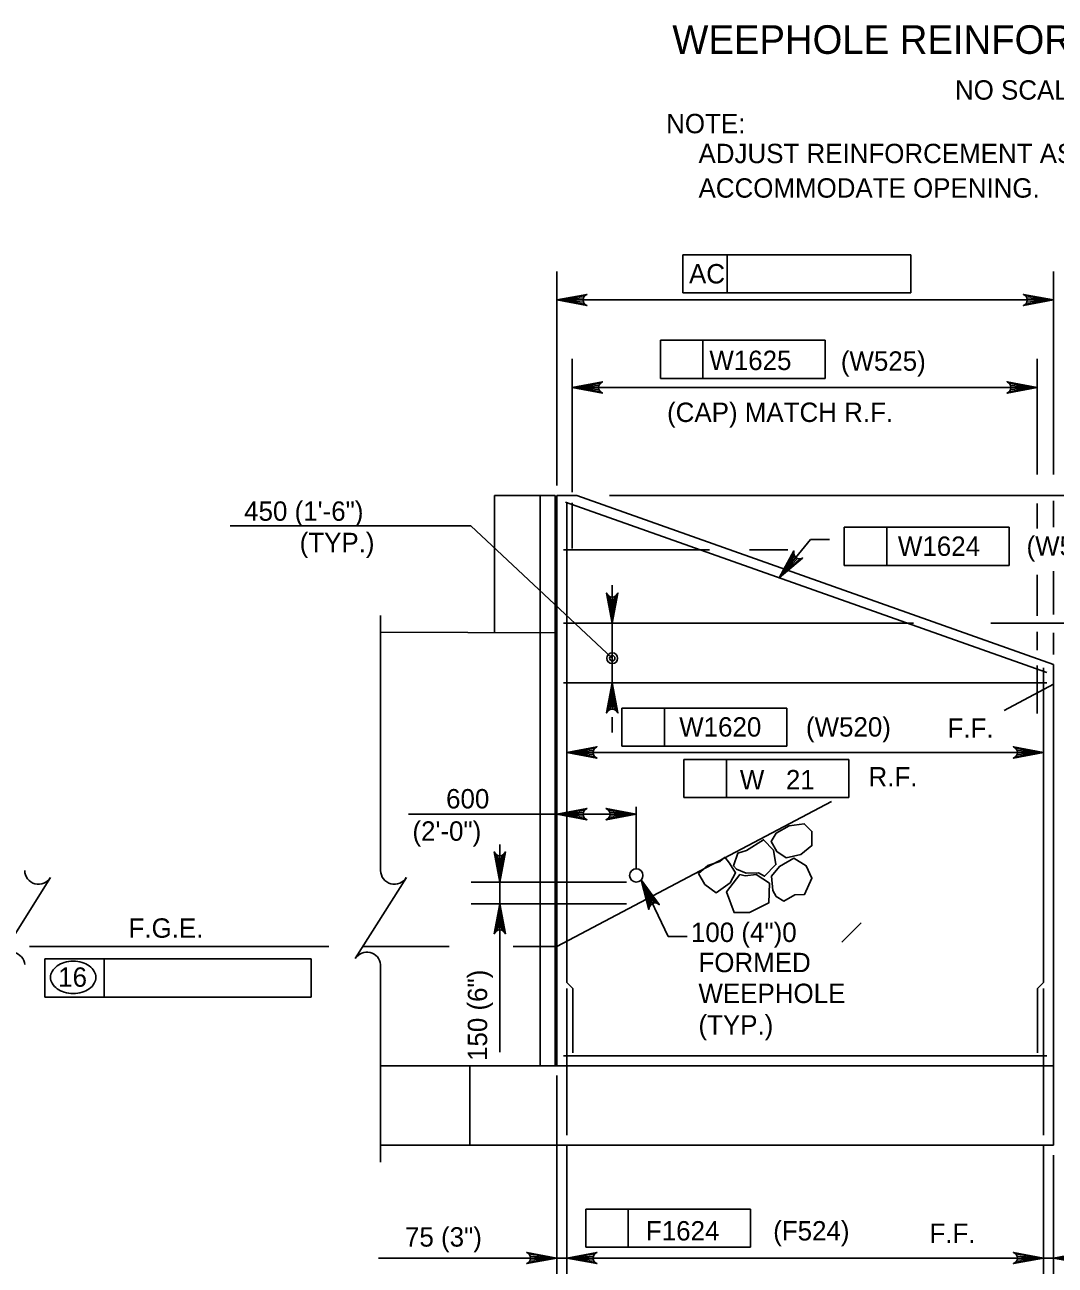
# Model space of a CAD drawing. Extents: x 638340 to 640241, y 295465 to 298435.
# Drawn here: x 639576.7 to 639736.2, y 297942.1 to 298134.1 of the extents above; entities that cross this region are included whole.
import ezdxf

# ---------------------------------------------------------------- set-up
doc = ezdxf.new("R2010")
doc.units = 0
for name, color, linetype in [('10', 7, 'Continuous'), ('3', 7, 'Continuous'), ('4', 7, 'Continuous'), ('5', 7, 'Continuous'), ('6', 7, 'Continuous')]:
    doc.layers.add(name, color=color, linetype=linetype)

# ---------------------------------------------------------------- blocks, each defined once
blk = doc.blocks.new('ROCK')
at = {"layer": '4'}
for points in [[(2.36725, 1.088), (2.2065, 0.82625), (2.378625, 0.506625), (2.66975, 0.3095), (3.128875, 0.403375), (3.48475, 0.6775), (3.4915, 1.123375), (3.25625, 1.36725), (2.783625, 1.308375)], [(1.10175, -0.02725), (1.4015, -0.159125), (1.78825, -0.148875), (1.980875, -0.266), (2.343375, 0.09475), (2.27875, 0.5505), (1.969375, 0.883), (1.4225, 0.553625), (1.152875, 0.479), (1.0105, 0.082)], [(0.74675, 0.359875), (0.882, 0.16), (1.072875, -0.144), (0.892, -0.457375), (0.448125, -0.758625), (0.1, -0.49325), (-0.095, -0.146375), (0.202875, 0.1025), (0.579125, 0.219875)], [(2.231375, -0.71725), (2.2025, -0.266375), (2.45475, 0.037125), (2.9085, 0.28875), (3.2995, 0.047625), (3.46875, -0.344), (3.231625, -0.855), (2.92, -0.860375), (2.5765, -1.054625), (2.340375, -0.904375)], [(1.2085, -0.192875), (0.778375, -0.737625), (1.008375, -1.391375), (1.48725, -1.396875), (2.09825, -1.106625), (2.133375, -0.486375), (1.723125, -0.203375), (1.37425, -0.239875)]]:
    blk.add_lwpolyline(points, close=True, dxfattribs=at)

msp = doc.modelspace()

# ---------------------------------------------------------------- linework, layer by layer
at = {"layer": '10'}
for p, q in [((639658.78, 298061.25), (639649.36, 298061.25)), ((639649.36, 298061.25), (639649.36, 298039.98)), ((639656.44, 298061.25), (639656.44, 297972.97)), ((639658.78, 298061.25), (639658.78, 297972.97)), ((639659.03, 298061.25), (639659.03, 297972.97)), ((639662.11, 298061.25), (639659.03, 298061.25)), ((639735.93, 298035.1), (639662.11, 298061.25)), ((639631.76, 298040.08), (639658.78, 298039.96)), ((639735.93, 298035.1), (639735.93, 297960.67)), ((639728.27, 298027.98), (639735.93, 298032.03)), ((639659.03, 297991.43), (639701.57, 298013.89)), ((639629.01, 297991.43), (639642.39, 297991.43)), ((639652.28, 297991.43), (639659.03, 297991.43)), ((639631.76, 297972.97), (639735.93, 297972.97)), ((639645.56, 297972.97), (639645.56, 297960.67)), ((639631.76, 297960.67), (639735.93, 297960.67))]:
    msp.add_line(p, q, dxfattribs=at)
at = {"layer": '3'}
for p, q in [((639645.74, 298056.56), (639608.46, 298056.56)), ((639631.76, 298042.66), (639631.76, 298003.19)), ((639580.65, 298002.12), (639572.75, 297989.56)), ((639635.74, 298002.12), (639627.83, 297989.56)), ((639631.76, 297988.62), (639631.76, 297958.04))]:
    msp.add_line(p, q, dxfattribs=at)
for radius in [0.833, 0.417]:
    msp.add_circle((639667.62, 298036.05), radius, dxfattribs=at)
for centre, start, end in [((639578.8, 298003.19), 180, 330), ((639633.89, 298003.19), 180, 330), ((639574.55, 297988.42), 5.3286, 147.8672), ((639629.64, 297988.42), 5.3286, 147.8672)]:
    msp.add_arc(centre, 2.13, start, end, dxfattribs=at)
at = {"layer": '4'}
for p, q in [((639678.55, 298098.51), (639713.86, 298098.51)), ((639678.55, 298092.6), (639678.55, 298098.51)), ((639685.4, 298092.6), (639685.4, 298098.51)), ((639713.86, 298098.51), (639713.86, 298092.6)), ((639659.03, 298062.79), (639659.03, 298095.94)), ((639735.93, 298064.49), (639735.93, 298095.94)), ((639713.86, 298092.6), (639678.55, 298092.6)), ((639661.98, 298091.52), (639732.98, 298091.52)), ((639675.06, 298085.27), (639700.6, 298085.27)), ((639675.06, 298079.36), (639675.06, 298085.27)), ((639681.66, 298079.36), (639681.66, 298085.27)), ((639700.6, 298085.27), (639700.6, 298079.36)), ((639661.43, 298061.76), (639661.43, 298082.41)), ((639733.4, 298064.49), (639733.4, 298082.41)), ((639700.6, 298079.36), (639675.06, 298079.36)), ((639661.43, 298077.98), (639733.4, 298077.98)), ((639667.17, 298061.25), (639852.81, 298061.25)), ((639733.4, 298056.16), (639733.4, 298060.02)), ((639735.93, 298056.36), (639735.93, 298060.42)), ((639645.74, 298056.56), (639667.62, 298036.05)), ((639703.53, 298056.32), (639729.07, 298056.32)), ((639703.53, 298050.41), (639703.53, 298056.32)), ((639710.13, 298050.41), (639710.13, 298056.32)), ((639729.07, 298056.32), (639729.07, 298050.41)), ((639693.44, 298048.52), (639698.32, 298054.42)), ((639698.32, 298054.42), (639701.27, 298054.42)), ((639688.88, 298052.84), (639694.81, 298052.84)), ((639729.07, 298050.41), (639703.53, 298050.41)), ((639733.4, 298042.61), (639733.4, 298048.98)), ((639735.93, 298042.81), (639735.93, 298049.55)), ((639667.62, 298044.42), (639667.62, 298047.37)), ((639667.62, 298041.47), (639667.62, 298032.24)), ((639726.21, 298041.47), (639740.19, 298041.47)), ((639733.4, 298037.32), (639733.4, 298040.13)), ((639735.93, 298036.64), (639735.93, 298039.99)), ((639669.1, 298028.34), (639694.64, 298028.34)), ((639669.1, 298022.43), (639669.1, 298028.34)), ((639675.69, 298022.43), (639675.69, 298028.34)), ((639694.64, 298028.34), (639694.64, 298022.43)), ((639667.62, 298026.92), (639667.62, 298024.53)), ((639660.57, 298021.47), (639734.39, 298021.47)), ((639694.64, 298022.43), (639669.1, 298022.43)), ((639678.72, 298020.4), (639704.26, 298020.4)), ((639678.72, 298014.49), (639678.72, 298020.4)), ((639685.31, 298014.49), (639685.31, 298020.4)), ((639704.26, 298020.4), (639704.26, 298014.49)), ((639704.26, 298014.49), (639678.72, 298014.49)), ((639636.07, 298011.92), (639671.34, 298011.92)), ((639671.34, 298003.45), (639671.34, 298013.06)), ((639650.21, 297975.06), (639650.21, 298007.2)), ((639669.8, 298001.4), (639645.78, 298001.4)), ((639672.11, 298001.75), (639676.25, 297992.96)), ((639669.8, 297998.05), (639645.78, 297998.05)), ((639703.14, 297992.09), (639706.13, 297995.08)), ((639676.25, 297992.96), (639679.2, 297992.96)), ((639623.75, 297991.43), (639577.42, 297991.43)), ((639579.79, 297989.49), (639621, 297989.49)), ((639579.79, 297983.59), (639579.79, 297989.49)), ((639588.96, 297983.59), (639588.96, 297989.49)), ((639621, 297989.49), (639621, 297983.59)), ((639621, 297983.59), (639579.79, 297983.59)), ((639659.03, 297971.43), (639659.03, 297938.76)), ((639660.57, 297960.67), (639660.57, 297938.76)), ((639734.39, 297960.67), (639734.39, 297938.76)), ((639735.93, 297959.13), (639735.93, 297938.76)), ((639663.5, 297950.78), (639689.04, 297950.78)), ((639663.5, 297944.88), (639663.5, 297950.78)), ((639670.09, 297944.88), (639670.09, 297950.78)), ((639689.04, 297950.78), (639689.04, 297944.88)), ((639689.04, 297944.88), (639663.5, 297944.88)), ((639653.13, 297943.19), (639631.42, 297943.19)), ((639656.08, 297943.19), (639653.13, 297943.19)), ((639660.57, 297943.19), (639659.03, 297943.19)), ((639659.91, 297943.19), (639662.87, 297943.19)), ((639663.52, 297943.19), (639731.44, 297943.19)), ((639663.52, 297943.19), (639666.48, 297943.19)), ((639731.44, 297943.19), (639728.49, 297943.19)), ((639734.39, 297943.19), (639735.93, 297943.19))]:
    msp.add_line(p, q, dxfattribs=at)
for points in [[(639659.03, 298091.52), (639663.69, 298092.39), (639663.33, 298092.14), (639663.15, 298091.83), (639663.1, 298091.52), (639663.15, 298091.2), (639663.33, 298090.89), (639663.69, 298090.64), (639659.03, 298091.52), (639663.33, 298090.89), (639663.15, 298091.2), (639659.03, 298091.52), (639663.1, 298091.52), (639663.15, 298091.83), (639659.03, 298091.52), (639663.33, 298092.14)], [(639735.93, 298091.52), (639731.27, 298090.64), (639731.63, 298090.89), (639731.81, 298091.2), (639731.87, 298091.52), (639731.81, 298091.83), (639731.63, 298092.14), (639731.27, 298092.39), (639735.93, 298091.52), (639731.63, 298092.14), (639731.81, 298091.83), (639735.93, 298091.52), (639731.87, 298091.52), (639731.81, 298091.2), (639735.93, 298091.52), (639731.63, 298090.89)], [(639661.43, 298077.98), (639666.09, 298078.86), (639665.73, 298078.61), (639665.55, 298078.3), (639665.49, 298077.98), (639665.55, 298077.67), (639665.73, 298077.36), (639666.09, 298077.11), (639661.43, 298077.98), (639665.73, 298077.36), (639665.55, 298077.67), (639661.43, 298077.98), (639665.49, 298077.98), (639665.55, 298078.3), (639661.43, 298077.98), (639665.73, 298078.61)], [(639733.4, 298077.98), (639728.74, 298077.11), (639729.1, 298077.36), (639729.28, 298077.67), (639729.34, 298077.98), (639729.28, 298078.3), (639729.1, 298078.61), (639728.74, 298078.86), (639733.4, 298077.98), (639729.1, 298078.61), (639729.28, 298078.3), (639733.4, 298077.98), (639729.34, 298077.98), (639729.28, 298077.67), (639733.4, 298077.98), (639729.1, 298077.36)], [(639693.44, 298048.52), (639695.73, 298052.67), (639695.7, 298052.24), (639695.82, 298051.89), (639696.03, 298051.65), (639696.3, 298051.49), (639696.66, 298051.44), (639697.08, 298051.56), (639693.44, 298048.52), (639696.66, 298051.44), (639696.3, 298051.49), (639693.44, 298048.52), (639696.03, 298051.65), (639695.82, 298051.89), (639693.44, 298048.52), (639695.7, 298052.24)], [(639667.62, 298041.47), (639666.75, 298046.13), (639666.99, 298045.77), (639667.31, 298045.58), (639667.62, 298045.53), (639667.93, 298045.58), (639668.24, 298045.77), (639668.49, 298046.13), (639667.62, 298041.47), (639668.24, 298045.77), (639667.93, 298045.58), (639667.62, 298041.47), (639667.62, 298045.53), (639667.31, 298045.58), (639667.62, 298041.47), (639666.99, 298045.77)], [(639667.62, 298032.24), (639668.49, 298027.58), (639668.24, 298027.94), (639667.93, 298028.12), (639667.62, 298028.18), (639667.31, 298028.12), (639666.99, 298027.94), (639666.75, 298027.58), (639667.62, 298032.24), (639666.99, 298027.94), (639667.31, 298028.12), (639667.62, 298032.24), (639667.62, 298028.18), (639667.93, 298028.12), (639667.62, 298032.24), (639668.24, 298027.94)], [(639660.57, 298021.47), (639665.23, 298022.34), (639664.87, 298022.09), (639664.69, 298021.78), (639664.63, 298021.47), (639664.69, 298021.16), (639664.87, 298020.84), (639665.23, 298020.6), (639660.57, 298021.47), (639664.87, 298020.84), (639664.69, 298021.16), (639660.57, 298021.47), (639664.63, 298021.47), (639664.69, 298021.78), (639660.57, 298021.47), (639664.87, 298022.09)], [(639734.39, 298021.47), (639729.73, 298020.6), (639730.09, 298020.84), (639730.28, 298021.16), (639730.33, 298021.47), (639730.28, 298021.78), (639730.09, 298022.09), (639729.73, 298022.34), (639734.39, 298021.47), (639730.09, 298022.09), (639730.28, 298021.78), (639734.39, 298021.47), (639730.33, 298021.47), (639730.28, 298021.16), (639734.39, 298021.47), (639730.09, 298020.84)], [(639659.03, 298011.92), (639663.69, 298012.79), (639663.33, 298012.54), (639663.15, 298012.23), (639663.1, 298011.92), (639663.15, 298011.6), (639663.33, 298011.29), (639663.69, 298011.04), (639659.03, 298011.92), (639663.33, 298011.29), (639663.15, 298011.6), (639659.03, 298011.92), (639663.1, 298011.92), (639663.15, 298012.23), (639659.03, 298011.92), (639663.33, 298012.54)], [(639671.34, 298011.92), (639666.67, 298011.04), (639667.03, 298011.29), (639667.22, 298011.6), (639667.27, 298011.92), (639667.22, 298012.23), (639667.03, 298012.54), (639666.67, 298012.79), (639671.34, 298011.92), (639667.03, 298012.54), (639667.22, 298012.23), (639671.34, 298011.92), (639667.27, 298011.92), (639667.22, 298011.6), (639671.34, 298011.92), (639667.03, 298011.29)], [(639650.21, 298001.4), (639649.34, 298006.06), (639649.58, 298005.7), (639649.9, 298005.52), (639650.21, 298005.46), (639650.52, 298005.52), (639650.83, 298005.7), (639651.08, 298006.06), (639650.21, 298001.4), (639650.83, 298005.7), (639650.52, 298005.52), (639650.21, 298001.4), (639650.21, 298005.46), (639649.9, 298005.52), (639650.21, 298001.4), (639649.58, 298005.7)], [(639672.11, 298001.75), (639674.88, 297997.9), (639674.5, 297998.12), (639674.14, 297998.16), (639673.84, 297998.07), (639673.58, 297997.89), (639673.37, 297997.59), (639673.3, 297997.16), (639672.11, 298001.75), (639673.37, 297997.59), (639673.58, 297997.89), (639672.11, 298001.75), (639673.84, 297998.07), (639674.14, 297998.16), (639672.11, 298001.75), (639674.5, 297998.12)], [(639650.21, 297998.05), (639651.08, 297993.39), (639650.83, 297993.74), (639650.52, 297993.93), (639650.21, 297993.98), (639649.9, 297993.93), (639649.58, 297993.74), (639649.34, 297993.39), (639650.21, 297998.05), (639649.58, 297993.74), (639649.9, 297993.93), (639650.21, 297998.05), (639650.21, 297993.98), (639650.52, 297993.93), (639650.21, 297998.05), (639650.83, 297993.74)], [(639659.03, 297943.19), (639654.37, 297942.32), (639654.73, 297942.57), (639654.92, 297942.88), (639654.97, 297943.19), (639654.92, 297943.5), (639654.73, 297943.82), (639654.37, 297944.06), (639659.03, 297943.19), (639654.73, 297943.82), (639654.92, 297943.5), (639659.03, 297943.19), (639654.97, 297943.19), (639654.92, 297942.88), (639659.03, 297943.19), (639654.73, 297942.57)], [(639660.57, 297943.19), (639665.23, 297944.06), (639664.87, 297943.82), (639664.69, 297943.5), (639664.63, 297943.19), (639664.69, 297942.88), (639664.87, 297942.57), (639665.23, 297942.32), (639660.57, 297943.19), (639664.87, 297942.57), (639664.69, 297942.88), (639660.57, 297943.19), (639664.63, 297943.19), (639664.69, 297943.5), (639660.57, 297943.19), (639664.87, 297943.82)], [(639734.39, 297943.19), (639729.73, 297942.32), (639730.09, 297942.57), (639730.28, 297942.88), (639730.33, 297943.19), (639730.28, 297943.5), (639730.09, 297943.82), (639729.73, 297944.06), (639734.39, 297943.19), (639730.09, 297943.82), (639730.28, 297943.5), (639734.39, 297943.19), (639730.33, 297943.19), (639730.28, 297942.88), (639734.39, 297943.19), (639730.09, 297942.57)], [(639735.93, 297943.19), (639740.59, 297944.06), (639740.23, 297943.82), (639740.05, 297943.5), (639739.99, 297943.19), (639740.05, 297942.88), (639740.23, 297942.57), (639740.59, 297942.32), (639735.93, 297943.19), (639740.23, 297942.57), (639740.05, 297942.88), (639735.93, 297943.19), (639739.99, 297943.19), (639740.05, 297943.5), (639735.93, 297943.19), (639740.23, 297943.82)]]:
    msp.add_lwpolyline(points, dxfattribs=at)
for points in [[(639661.98, 298092.01), (639661.98, 298091.02), (639659.03, 298091.52)], [(639732.98, 298092.01), (639732.98, 298091.02), (639735.93, 298091.52)], [(639695.7, 298050.48), (639694.94, 298051.11), (639693.44, 298048.52)], [(639667.13, 298044.42), (639668.11, 298044.42), (639667.62, 298041.47)], [(639667.13, 298029.28), (639668.11, 298029.28), (639667.62, 298032.24)], [(639663.52, 298021.96), (639663.52, 298020.98), (639660.57, 298021.47)], [(639731.44, 298021.96), (639731.44, 298020.98), (639734.39, 298021.47)], [(639661.98, 298012.41), (639661.98, 298011.42), (639659.03, 298011.92)], [(639668.38, 298012.41), (639668.38, 298011.42), (639671.34, 298011.92)], [(639649.72, 298004.36), (639650.7, 298004.36), (639650.21, 298001.4)], [(639672.92, 297998.87), (639673.81, 297999.29), (639672.11, 298001.75)], [(639649.72, 297995.09), (639650.7, 297995.09), (639650.21, 297998.05)], [(639656.08, 297943.68), (639656.08, 297942.7), (639659.03, 297943.19)], [(639663.52, 297943.68), (639663.52, 297942.7), (639660.57, 297943.19)], [(639731.44, 297943.68), (639731.44, 297942.7), (639734.39, 297943.19)], [(639738.88, 297943.68), (639738.88, 297942.7), (639735.93, 297943.19)]]:
    msp.add_lwpolyline(points, close=True, dxfattribs=at)
msp.add_circle((639671.34, 298002.43), 1.03, dxfattribs=at)
for centre, radius, start, end in [((639583.82, 297985.45), 3.66, 106.5358, 125.6316), ((639584.17, 297984.29), 4.87, 90, 106.5358), ((639584.17, 297984.29), 4.87, 73.4642, 90), ((639584.51, 297985.45), 3.66, 54.3684, 73.4642), ((639582.49, 297986.65), 1.83, 149.9767, 180), ((639583.3, 297986.18), 2.76, 125.6316, 149.9767), ((639585.04, 297986.18), 2.76, 30.0233, 54.3684), ((639585.84, 297986.65), 1.83, 0, 30.0233), ((639582.49, 297986.65), 1.83, 180, 210.0233), ((639583.3, 297987.11), 2.76, 210.0233, 234.3684), ((639585.04, 297987.11), 2.76, 305.6316, 329.9767), ((639585.84, 297986.65), 1.83, 329.9767, 0), ((639583.82, 297987.85), 3.66, 234.3684, 253.4642), ((639584.17, 297989.01), 4.87, 253.4642, 270), ((639584.17, 297989.01), 4.87, 270, 286.5358), ((639584.51, 297987.85), 3.66, 286.5358, 305.6316)]:
    msp.add_arc(centre, radius, start, end, dxfattribs=at)
at = {"layer": '5'}
for p, q in [((639661.42, 298060.12), (639661.43, 298053.03)), ((639733.39, 298034.93), (639733.4, 298027.48))]:
    msp.add_line(p, q, dxfattribs=at)
at = {"layer": '6'}
for p, q in [((639734.9, 298033.84), (639660.4, 298060.22)), ((639660.57, 298060.22), (639660.57, 297985.84)), ((639660.06, 298052.84), (639682.65, 298052.84)), ((639660.06, 298041.47), (639714.26, 298041.47)), ((639734.39, 298034.56), (639734.39, 297985.84)), ((639660.06, 298032.24), (639734.9, 298032.24)), ((639660.57, 297985.84), (639661.51, 297984.91)), ((639660.57, 297984.91), (639660.57, 297962.21)), ((639661.51, 297984.91), (639661.51, 297974.97)), ((639734.39, 297985.84), (639733.46, 297984.91)), ((639733.46, 297984.91), (639733.46, 297974.97)), ((639734.39, 297984.91), (639734.39, 297962.21)), ((639660.06, 297974.51), (639734.9, 297974.51))]:
    msp.add_line(p, q, dxfattribs=at)

# ---------------------------------------------------------------- block references
at = {"layer": '4', "xscale": 4.921475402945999, "yscale": 4.921475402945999, "rotation": 0.8865726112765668}
msp.add_blockref('ROCK', (639681.42, 298003.45), dxfattribs=at)

# ---------------------------------------------------------------- texts
at = {"layer": '3'}
for s, height, p in [('450 (1\'-6")', 3.0001, (639610.63, 298057.33)), ('(TYP.)', 3, (639619.22, 298052.47)), ('100 (4")0', 3, (639679.8, 297992.12))]:
    msp.add_text(s, height=height, dxfattribs=at).set_placement(p)
at = {"layer": '4'}
for s, height, p in [('WEEPHOLE REINFORCEMENT DETAIL', 4.4294, (639676.91, 298129.62)), ('NO SCALE', 3, (639720.67, 298122.53)), ('NOTE:', 3, (639675.96, 298117.33)), ('ADJUST REINFORCEMENT AS NECESSARY TO', 3.0001, (639680.97, 298112.7)), ('ACCOMMODATE OPENING.', 3.0001, (639680.97, 298107.36)), ('AC', 3, (639679.5, 298094.08)), ('W1625', 3, (639682.65, 298080.67)), ('(W525)', 3, (639703, 298080.56)), ('(CAP) MATCH R.F.', 3.0001, (639676.1, 298072.63)), ('W1624', 3, (639711.84, 298051.9)), ('(W524)', 3, (639731.75, 298051.93)), ('W1620', 3, (639677.98, 298023.92)), ('(W520)', 3, (639697.6, 298023.92)), ('F.F.', 3, (639719.52, 298023.74)), ('W   21', 3, (639687.37, 298015.75)), ('R.F.', 3, (639707.28, 298016.2)), ('600', 3, (639641.89, 298012.8)), ('(2\'-0")', 3, (639636.68, 298007.8)), ('F.G.E.', 3, (639592.73, 297992.78)), ('FORMED', 3, (639680.96, 297987.45)), ('16', 3, (639581.84, 297985.19)), ('WEEPHOLE', 3, (639680.96, 297982.67)), ('(TYP.)', 3, (639680.96, 297977.79)), ('F1624', 3, (639672.83, 297945.91)), ('(F524)', 3, (639692.53, 297945.91)), ('F.F.', 3, (639716.71, 297945.52)), ('75 (3")', 3, (639635.53, 297944.96))]:
    msp.add_text(s, height=height, dxfattribs=at).set_placement(p)
msp.add_text('150 (6")', height=3, rotation=90, dxfattribs=at).set_placement((639648.25, 297973.7))

doc.saveas('drawing.dxf')
